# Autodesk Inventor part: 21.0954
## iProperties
Created: 2012-10
Part Number: 21.0954
Document SubType Name: Modeling
Designer: Administrator
Density: 2.71 g/cm^3
Description: ADAPTOR G32-G32
Stock Number: 21.0954 ADAPTOR G32-G32
Material: Aluminum-6061
Mass: 12.6123 g
Surface Area: 34.7342 cm^2
Volume: 4.654 cm^3
Author: Administrator
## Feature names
1. Base1
